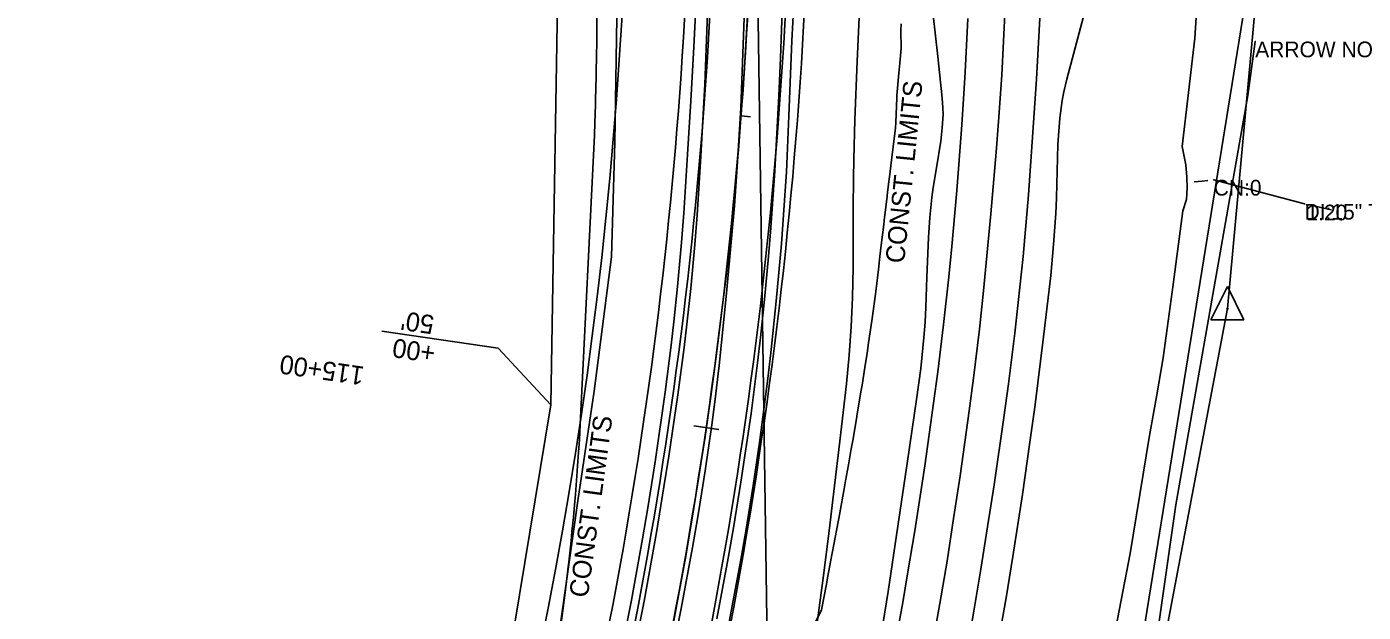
# Model space of a CAD drawing. Extents: x 1674300 to 1677920, y 225056 to 231852.
# Drawn here: x 1677145.4 to 1677571.2, y 228719.7 to 228906.3 of the extents above; entities that cross this region are included whole.
import ezdxf

# ---------------------------------------------------------------- set-up
doc = ezdxf.new("R2010")
doc.units = 0
for name, color, linetype in [('R_Annotation', 7, 'Continuous'), ('R_Horz Alg', 7, 'Continuous'), ('R_Horz Alg Annot', 7, 'Continuous'), ('R_Proposed Const Limits_Fill', 7, 'Continuous'), ('R_Proposed Road_Lane', 7, 'Continuous'), ('R_Proposed Road_Shoulder', 7, 'Continuous'), ('R_ROW', 7, 'Continuous'), ('R_ROW Annot', 7, 'Continuous'), ('S_DITCHLINE', 7, 'Continuous'), ('S_DRG_PT_SYM', 7, 'Continuous'), ('S_DROP_INLET_ANNOT', 7, 'Continuous'), ('S_EDGE_PAVEMENT', 7, 'Continuous'), ('S_ELECTRIC_UTILITIES', 7, 'Continuous'), ('S_EXIST_ROW', 7, 'Continuous'), ('S_EXISTING_ALIGNMENT', 7, 'Continuous'), ('S_FIBER_OPTIC_CABLE', 7, 'Continuous'), ('S_FIBER_OPTIC_CABLE_ANNOT', 7, 'Continuous'), ('S_PAVEMENT_CROWN', 7, 'Continuous'), ('S_SHOULDER', 7, 'Continuous'), ('S_SIDE_DRAIN', 7, 'Continuous'), ('S_SIDE_DRAIN_ANNOT', 7, 'Continuous'), ('S_UTL_PT_SYM', 7, 'Continuous')]:
    doc.layers.add(name, color=color, linetype=linetype)

msp = doc.modelspace()

# ---------------------------------------------------------------- linework, layer by layer
at = {"layer": 'R_Horz Alg'}
msp.add_arc((1675928.16, 228988.54), 1449, 296.0624, 0.80558, dxfattribs=at)
at = {"layer": 'R_Horz Alg Annot'}
msp.add_line((1677389.93, 228090.45), (1677377.01, 229008.91), dxfattribs=at)
for points in [[(1677375.92, 228877.65), (1677372.93, 228877.88)], [(1677357.9, 228779.09), (1677365.81, 228777.93)]]:
    msp.add_lwpolyline(points, dxfattribs=at)
at = {"layer": 'R_Proposed Const Limits_Fill'}
for points in [[(1677315.59, 228716.28), (1677316.13, 228720.29), (1677316.86, 228725.97), (1677317.07, 228727.67), (1677317.95, 228735.06), (1677318.02, 228735.68), (1677318.78, 228742.45), (1677319.08, 228745.39), (1677319.51, 228749.86), (1677319.98, 228755.12), (1677320.19, 228757.27), (1677320.75, 228764.69), (1677320.76, 228764.86), (1677321.28, 228772.11), (1677321.42, 228774.6), (1677321.64, 228779.55), (1677326.25, 228871.74), (1677326.38, 228875.68), (1677326.57, 228881.43), (1677326.62, 228883.05), (1677326.77, 228890.43), (1677326.78, 228891.11), (1677326.92, 228897.81), (1677326.95, 228900.8), (1677327, 228905.18), (1677327.04, 228910.48)], [(1677394.89, 228713.06), (1677398.57, 228720.36), (1677398.69, 228721), (1677400.02, 228728.08), (1677400.6, 228731.14), (1677401.49, 228735.8), (1677402.54, 228741.27), (1677402.95, 228743.52), (1677404.41, 228751.24), (1677404.44, 228751.42), (1677405.8, 228758.98), (1677406.25, 228761.58), (1677407.17, 228766.72), (1677408.05, 228771.74), (1677408.51, 228774.47), (1677409.78, 228781.93), (1677409.83, 228782.22), (1677411.14, 228789.98), (1677411.48, 228792.11), (1677412.38, 228797.75), (1677413.07, 228802.32), (1677413.55, 228805.53), (1677414.6, 228812.54), (1677414.71, 228813.31), (1677415.74, 228821.11), (1677415.96, 228822.78), (1677416.71, 228828.92), (1677417.18, 228833.04), (1677417.63, 228836.74), (1677418.4, 228843.3), (1677418.54, 228844.55), (1677419.45, 228852.37), (1677419.58, 228853.57), (1677420.44, 228860.19), (1677420.88, 228863.84), (1677421.36, 228868.01), (1677422.12, 228874.11), (1677422.3, 228875.84), (1677422.56, 228883.71), (1677422.56, 228884.44), (1677423.19, 228891.56), (1677423.49, 228894.74), (1677423.9, 228899.41), (1677423.87, 228905.08), (1677423.97, 228907.29)]]:
    msp.add_lwpolyline(points, dxfattribs=at)
at = {"layer": 'R_Proposed Road_Lane'}
for radius in [1437, 1461]:
    msp.add_arc((1675928.16, 228988.54), radius, 345.73457, 0.80558, dxfattribs=at)
at = {"layer": 'R_Proposed Road_Shoulder'}
for radius in [1429, 1467]:
    msp.add_arc((1675928.16, 228988.54), radius, 345.73457, 0.80558, dxfattribs=at)
at = {"layer": 'R_ROW'}
msp.add_lwpolyline([(1677280.82, 228594.47), (1677312.38, 228785.76), (1677312.38, 228785.76), (1677316.54, 229041.92), (1677294.58, 229181.63), (1677294.58, 229181.63)], dxfattribs=at)
at = {"layer": 'R_ROW Annot'}
for p, q in [((1677295.58, 228803.87), (1677258.54, 228809.29)), ((1677312.38, 228785.76), (1677295.58, 228803.87))]:
    msp.add_line(p, q, dxfattribs=at)
at = {"layer": 'S_DITCHLINE'}
for points in [[(1677492.32, 228714.69), (1677496.91, 228738.44), (1677499.97, 228757.22), (1677503.03, 228775.99), (1677505.25, 228788.38), (1677507.46, 228800.77), (1677510.6, 228824.19), (1677513.73, 228847.61), (1677514.83, 228851.31), (1677515.02, 228854.93), (1677514.96, 228858.41), (1677514.63, 228862.29), (1677513.48, 228868.18), (1677515.51, 228885.41), (1677517.54, 228902.65), (1677519.12, 228927.5), (1677520.71, 228952.35), (1677519.88, 228976.18), (1677519.06, 229000), (1677520.55, 229018.83), (1677522.04, 229037.67)], [(1677396.31, 228709.99), (1677399.2, 228731.39), (1677401.02, 228745.66), (1677402.74, 228759.95), (1677404.46, 228774.25), (1677406.5, 228792.49), (1677407.36, 228801.62), (1677408.03, 228810.76), (1677408.27, 228815.34), (1677408.46, 228820.07), (1677408.64, 228829.53), (1677408.68, 228848.46), (1677408.72, 228857.93), (1677408.82, 228864.16), (1677409.19, 228876.62), (1677409.97, 228895.31), (1677410.76, 228913.99)], [(1677517.33, 228856.94), (1677519.88, 228857.15), (1677521.64, 228857.29)], [(1677561.01, 228848), (1677553.85, 228849.54)]]:
    msp.add_lwpolyline(points, dxfattribs=at)
at = {"layer": 'S_DRG_PT_SYM'}
for points in [[(1677523.52, 228857.52), (1677523.52, 228857.57), (1677523.52, 228857.52), (1677523.47, 228857.52), (1677523.52, 228857.52), (1677523.52, 228857.47), (1677523.52, 228857.52), (1677523.57, 228857.52)], [(1677552.48, 228849.85), (1677552.48, 228849.9), (1677552.48, 228849.85), (1677552.43, 228849.85), (1677552.48, 228849.85), (1677552.48, 228849.8), (1677552.48, 228849.85), (1677552.53, 228849.85)], [(1677553.05, 228849.61), (1677553.05, 228849.66), (1677553.05, 228849.61), (1677553, 228849.61), (1677553.05, 228849.61), (1677553.05, 228849.56), (1677553.05, 228849.61), (1677553.1, 228849.61)]]:
    msp.add_lwpolyline(points, dxfattribs=at)
at = {"layer": 'S_EDGE_PAVEMENT'}
for points in [[(1677339.36, 228709.5), (1677342.05, 228723.2), (1677345.99, 228745.08), (1677348.39, 228759.7), (1677349.91, 228769.47), (1677352.76, 228789.02), (1677354.78, 228804.04), (1677355.71, 228811.56), (1677356.95, 228822.86), (1677358.22, 228836.91), (1677358.93, 228846.29), (1677360.12, 228865.08), (1677361.35, 228887.92), (1677361.87, 228899.35), (1677362.5, 228916.49)], [(1677365.25, 228717.56), (1677368.85, 228736.91), (1677370.53, 228746.61), (1677372.91, 228761.18), (1677376.12, 228783.09), (1677378.21, 228799.21), (1677379.16, 228807.28), (1677380.44, 228819.41), (1677381.69, 228833.07), (1677382.41, 228842.19), (1677383.66, 228860.44), (1677384.96, 228884.35), (1677385.49, 228896.31), (1677386.11, 228914.25)], [(1677443.55, 228699.98), (1677447.09, 228720.05), (1677449.33, 228733.45), (1677451.44, 228746.87), (1677453.55, 228760.29), (1677456.69, 228781.76), (1677458.15, 228792.51), (1677460.17, 228808.65), (1677461.79, 228823.32), (1677462.77, 228833.1), (1677464.48, 228852.7), (1677465.41, 228864.99), (1677467.02, 228889.58), (1677468.3, 228912.92)], [(1677421.11, 228704.51), (1677424.43, 228722.78), (1677426.02, 228731.93), (1677428.3, 228745.66), (1677431.48, 228766.31), (1677434.3, 228786.31), (1677435.61, 228796.33), (1677437.42, 228811.37), (1677438.99, 228825.61), (1677439.95, 228835.12), (1677441.69, 228854.14), (1677443.21, 228873.55), (1677443.86, 228883.26), (1677444.36, 228891.83), (1677445.2, 228908.97)]]:
    msp.add_lwpolyline(points, dxfattribs=at)
at = {"layer": 'S_ELECTRIC_UTILITIES'}
msp.add_line((1677492.08, 228657.14), (1677537.01, 228935.14), dxfattribs=at)
at = {"layer": 'S_EXIST_ROW'}
for p, q in [((1677527.92, 228816.46), (1677555.5, 229117.02)), ((1677527.94, 228823.55), (1677522.65, 228812.91)), ((1677527.94, 228823.55), (1677533.17, 228812.91)), ((1677507.28, 228707.44), (1677527.92, 228816.46)), ((1677527.92, 228816.46), (1677527.92, 228816.46)), ((1677522.65, 228812.91), (1677533.17, 228812.91))]:
    msp.add_line(p, q, dxfattribs=at)
for radius in [0.18, 0.09]:
    msp.add_circle((1677527.92, 228816.46), radius, dxfattribs=at)
msp.add_arc((1675926.71, 228989.39), 1410.53, 295.94359, 0.85682, dxfattribs=at)
at = {"layer": 'S_EXISTING_ALIGNMENT'}
msp.add_arc((1675926.71, 228989.39), 1450.53, 345.81316, 0.85682, dxfattribs=at)
at = {"layer": 'S_FIBER_OPTIC_CABLE'}
for p, q in [((1677332.71, 228869.56), (1677333.73, 228928.6)), ((1677534.42, 228884.38), (1677536.75, 228901.6)), ((1677511.42, 228753.9), (1677534.42, 228884.38)), ((1677331.7, 228832.96), (1677332.71, 228869.56)), ((1677326.19, 228790.16), (1677331.7, 228832.96)), ((1677320.94, 228755.15), (1677326.19, 228790.16)), ((1677312.48, 228695.6), (1677320.94, 228755.15)), ((1677501.74, 228685.3), (1677511.42, 228753.9))]:
    msp.add_line(p, q, dxfattribs=at)
at = {"layer": 'S_PAVEMENT_CROWN'}
for points in [[(1677350.13, 228702.03), (1677353.81, 228720.85), (1677357.42, 228740.33), (1677359.12, 228750.09), (1677361.52, 228764.75), (1677363.66, 228779.45), (1677364.63, 228786.81), (1677365.98, 228798.32), (1677368.32, 228821.37), (1677370.04, 228839.97), (1677370.82, 228849.28), (1677371.84, 228863.25), (1677372.82, 228880.51), (1677373.32, 228892.02), (1677374.14, 228915.06)], [(1677432.69, 228702.16), (1677436.31, 228722.44), (1677438.56, 228735.98), (1677440.65, 228749.55), (1677442.74, 228763.12), (1677445.66, 228783.88), (1677447.01, 228794.27), (1677448.87, 228809.88), (1677450.17, 228822.13), (1677452.49, 228846.67), (1677454.21, 228866.32), (1677454.98, 228876.16), (1677455.99, 228890.92), (1677457.05, 228912.61)]]:
    msp.add_lwpolyline(points, dxfattribs=at)
at = {"layer": 'S_SHOULDER'}
for points in [[(1677335.43, 228710.27), (1677338, 228723.56), (1677341.54, 228743.12), (1677343.2, 228752.93), (1677345.54, 228767.65), (1677348.74, 228789.8), (1677350.66, 228804.77), (1677351.54, 228812.27), (1677352.72, 228823.53), (1677353.95, 228837.54), (1677354.66, 228846.89), (1677355.9, 228865.59), (1677356.91, 228882.73), (1677357.91, 228899.87), (1677358.7, 228917.02)], [(1677369.13, 228716.61), (1677372.74, 228735.88), (1677374.42, 228745.53), (1677376.78, 228760.04), (1677378.93, 228774.58), (1677379.92, 228781.87), (1677381.46, 228794.18), (1677382.4, 228802.4), (1677384.13, 228818.87), (1677385.8, 228837.17), (1677386.51, 228846.33), (1677387.39, 228860.08), (1677388.2, 228877.96), (1677389.14, 228901.8), (1677389.78, 228913.71)], [(1677417.54, 228712.44), (1677419.8, 228726.27), (1677422.86, 228747.08), (1677425.93, 228767.89), (1677428.88, 228787.54), (1677430.18, 228797.38), (1677431.2, 228807.23), (1677431.57, 228812.17), (1677431.83, 228816.92), (1677432.17, 228826.45), (1677432.64, 228839.16), (1677433.05, 228845.52), (1677433.69, 228851.87), (1677434.11, 228855.04), (1677435.17, 228861.4), (1677436.58, 228869.86), (1677437.06, 228874.09), (1677437.29, 228878.32), (1677437.27, 228880.43), (1677437.04, 228883.6), (1677435.59, 228896.81), (1677434.14, 228910.02)], [(1677455.02, 228711.19), (1677457.35, 228724.31), (1677459.53, 228737.45), (1677462.59, 228757.21), (1677464.98, 228773.94), (1677466.49, 228785.1), (1677469.34, 228807.44), (1677471.62, 228827.07), (1677472.53, 228836.91), (1677473.2, 228846.8), (1677473.42, 228851.77), (1677473.91, 228868.78), (1677474.26, 228874.41), (1677474.52, 228877.22), (1677475.26, 228882.78), (1677475.77, 228885.55), (1677476.72, 228889.65), (1677482.34, 228910.72)]]:
    msp.add_lwpolyline(points, dxfattribs=at)
at = {"layer": 'S_SIDE_DRAIN'}
msp.add_line((1677552.48, 228849.85), (1677523.52, 228857.52), dxfattribs=at)
at = {"layer": 'S_UTL_PT_SYM'}
for points in [[(1677536.75, 228901.6), (1677536.75, 228901.65), (1677536.75, 228901.6), (1677536.7, 228901.6), (1677536.75, 228901.6), (1677536.75, 228901.55), (1677536.75, 228901.6), (1677536.8, 228901.6)], [(1677534.42, 228884.38), (1677534.42, 228884.43), (1677534.42, 228884.38), (1677534.37, 228884.38), (1677534.42, 228884.38), (1677534.42, 228884.33), (1677534.42, 228884.38), (1677534.47, 228884.38)], [(1677332.71, 228869.56), (1677332.71, 228869.61), (1677332.71, 228869.56), (1677332.66, 228869.56), (1677332.71, 228869.56), (1677332.71, 228869.51), (1677332.71, 228869.56), (1677332.76, 228869.56)], [(1677331.7, 228832.96), (1677331.7, 228833.01), (1677331.7, 228832.96), (1677331.65, 228832.96), (1677331.7, 228832.96), (1677331.7, 228832.91), (1677331.7, 228832.96), (1677331.75, 228832.96)], [(1677326.19, 228790.16), (1677326.19, 228790.21), (1677326.19, 228790.16), (1677326.14, 228790.16), (1677326.19, 228790.16), (1677326.19, 228790.11), (1677326.19, 228790.16), (1677326.24, 228790.16)], [(1677320.94, 228755.15), (1677320.94, 228755.2), (1677320.94, 228755.15), (1677320.89, 228755.15), (1677320.94, 228755.15), (1677320.94, 228755.1), (1677320.94, 228755.15), (1677320.99, 228755.15)], [(1677511.42, 228753.9), (1677511.42, 228753.95), (1677511.42, 228753.9), (1677511.37, 228753.9), (1677511.42, 228753.9), (1677511.42, 228753.85), (1677511.42, 228753.9), (1677511.47, 228753.9)]]:
    msp.add_lwpolyline(points, dxfattribs=at)

# ---------------------------------------------------------------- texts
at = {"layer": 'R_Annotation'}
for rotation, p in [(84.2111, (1677424.89, 228830.72)), (82.2016, (1677324.09, 228724.12))]:
    msp.add_text('CONST. LIMITS', height=6, rotation=rotation, dxfattribs=at).set_placement(p)
at = {"layer": 'R_Horz Alg Annot'}
msp.add_text('115+00', height=6, rotation=171.6658, dxfattribs=at).set_placement((1677253.18, 228797.89))
at = {"layer": 'R_ROW Annot'}
for s, p in [("50'", (1677275.48, 228814.19)), ('+00', (1677275.87, 228805.03))]:
    msp.add_text(s, height=6, rotation=171.619, dxfattribs=at).set_placement(p)
at = {"layer": 'S_DROP_INLET_ANNOT'}
msp.add_text('1.20', height=5, dxfattribs=at).set_placement((1677553.05, 228844.61))
at = {"layer": 'S_FIBER_OPTIC_CABLE_ANNOT'}
msp.add_text('ARROW NORTH', height=5, dxfattribs=at).set_placement((1677536.75, 228896.6))
at = {"layer": 'S_SIDE_DRAIN_ANNOT'}
for s, p in [('CN:0', (1677523.52, 228852.52)), ('DI:15" TY:CMP CN:0', (1677552.48, 228844.85))]:
    msp.add_text(s, height=5, dxfattribs=at).set_placement(p)

doc.saveas('drawing.dxf')
